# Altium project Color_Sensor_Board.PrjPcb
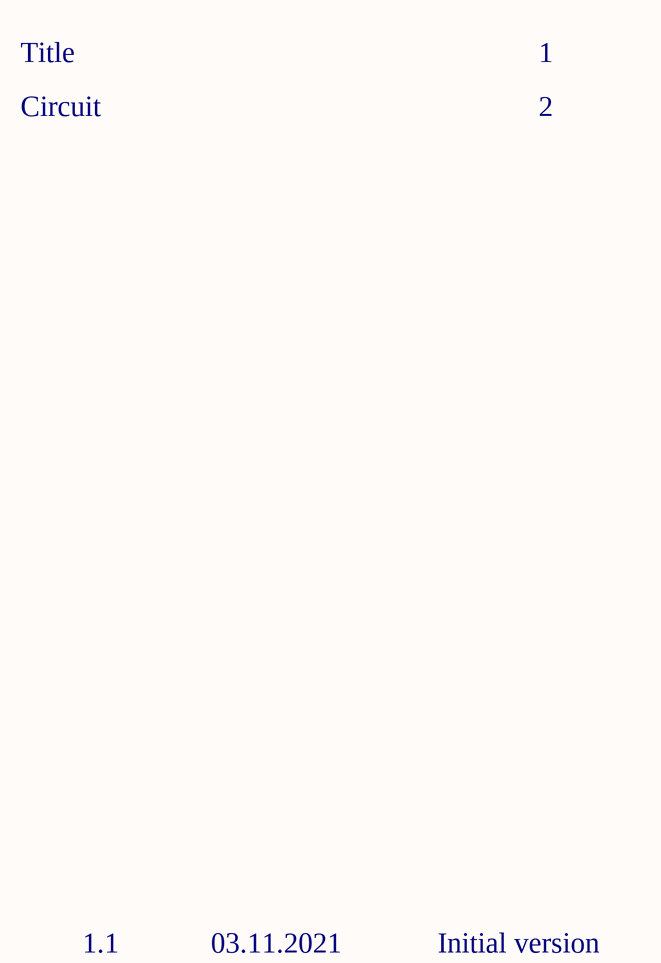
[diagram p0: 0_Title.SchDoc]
2 sheets, 38 parts. Net scope: global (net labels, ports and power ports of the same name join across sheets).
Board file: Color_Sensor_Board.PcbDoc
Sheets:
  0_Title.SchDoc
  1_Circuit.SchDoc

## Sheet 0_Title.SchDoc: Title
size A2; Author: Aleksandr Dudko; Engineer: Engineer; Organization: Softeq Development; Revision: 1.1.2; SheetNumber: 1; SheetTotal: 2; Project: Color_Sensor_Board; Reviewed: YES; Approved: YES

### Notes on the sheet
- Title
- 1
- Circuit
- 2
- 1.1
- 03.11.2021
- Initial version

## Sheet 1_Circuit.SchDoc: Circuit
size A2; Author: Aleksandr Dudko; Engineer: Engineer; Organization: Softeq Development; Revision: 1.1.2; SheetNumber: 2; SheetTotal: 2; Project: Color_Sensor_Board; Reviewed: YES; Approved: YES
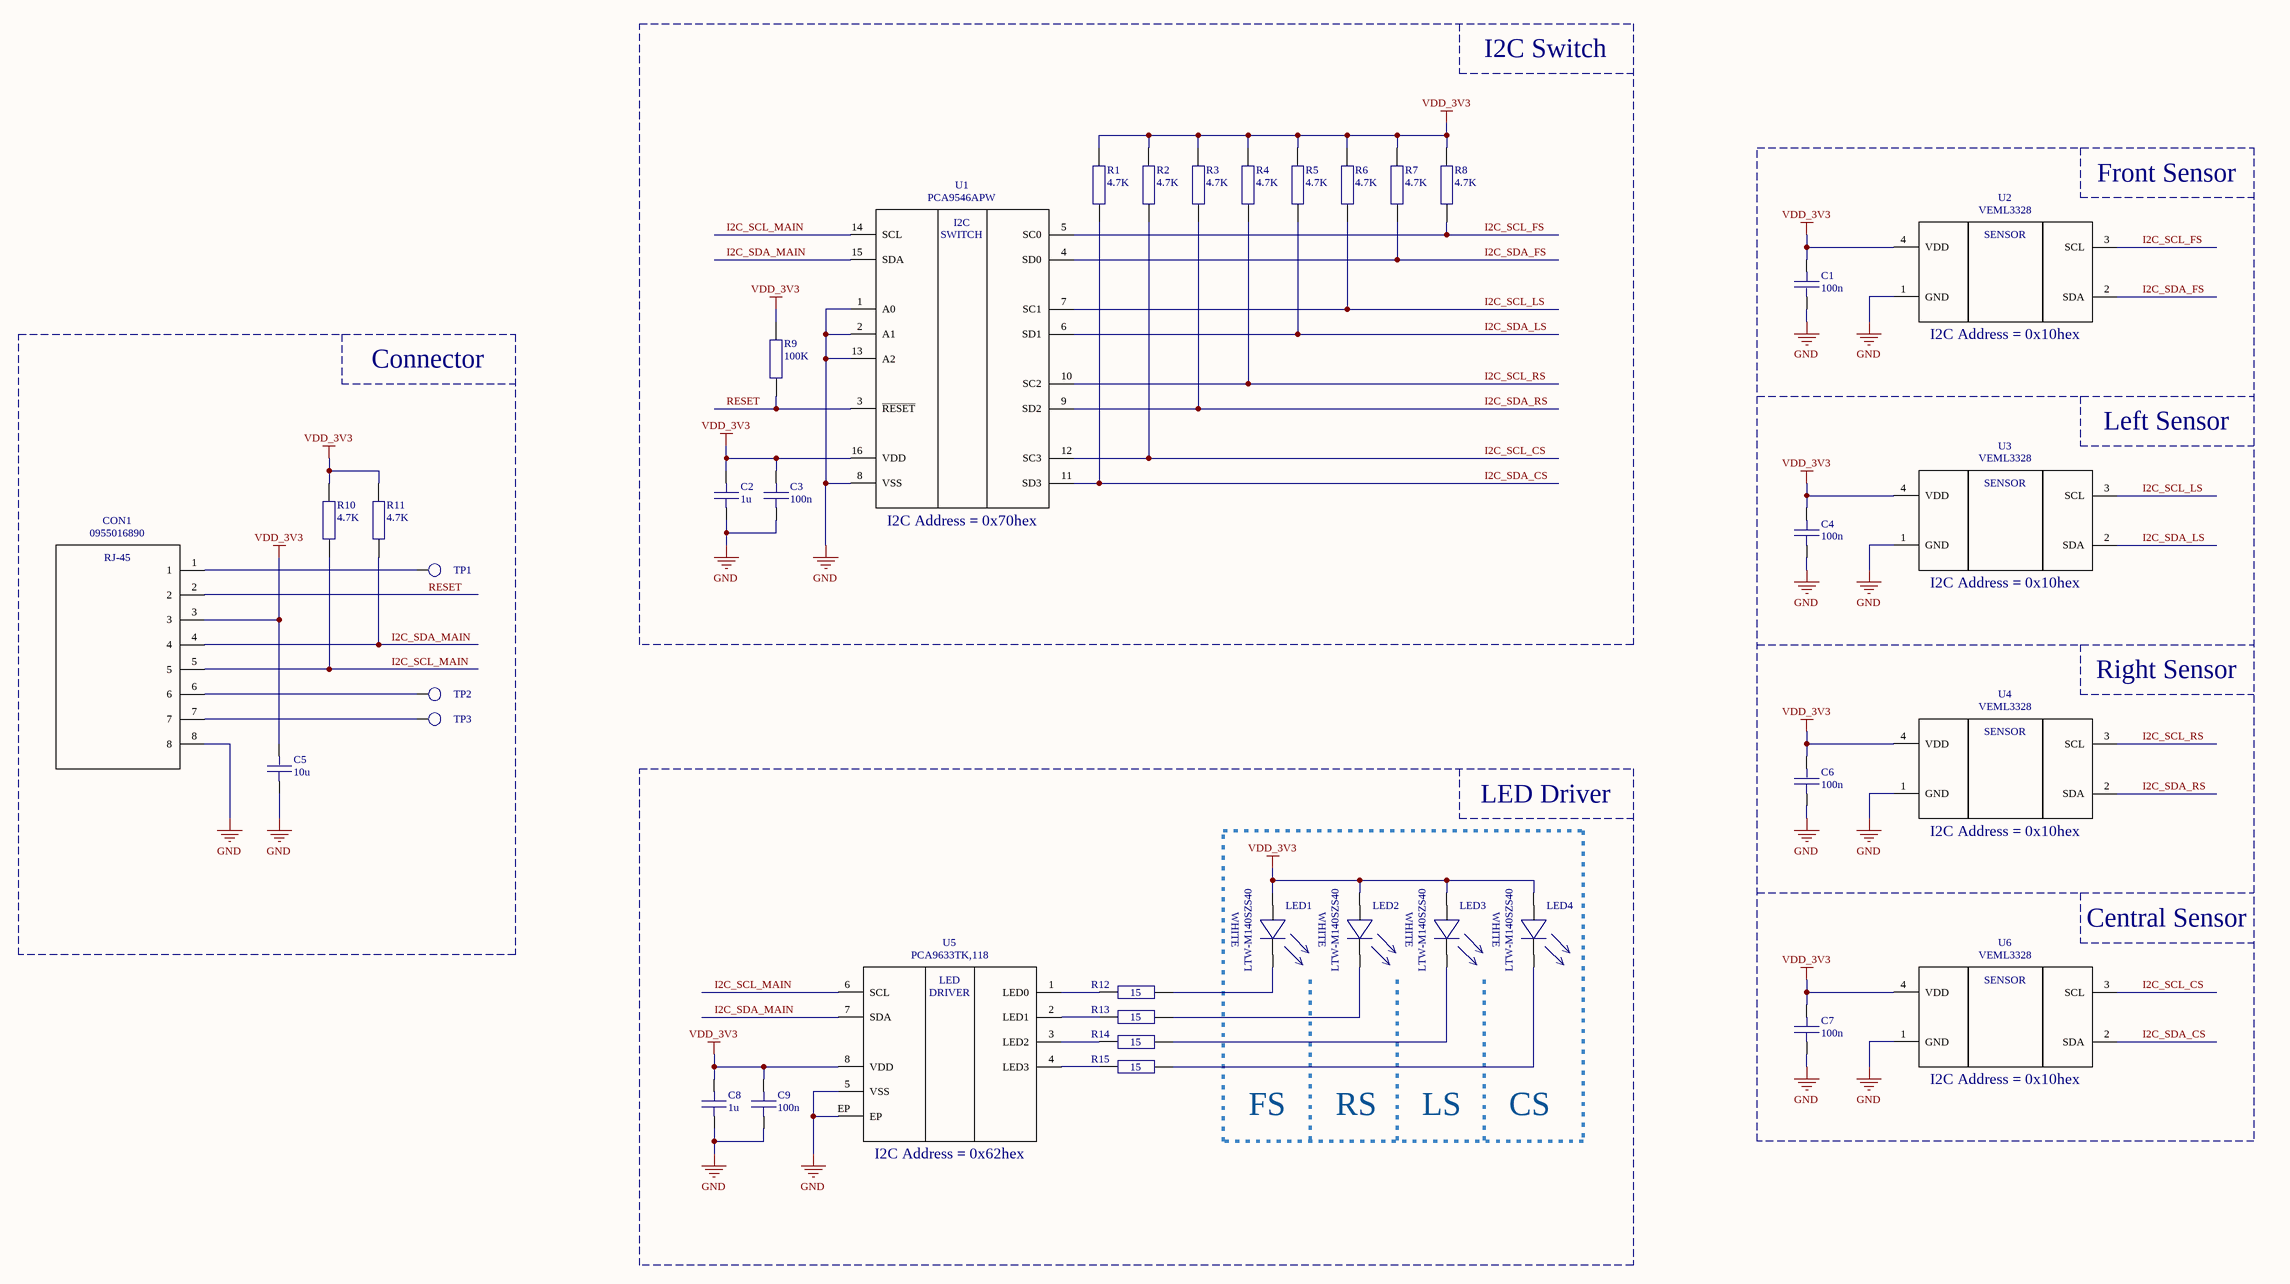
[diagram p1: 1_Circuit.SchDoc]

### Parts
C1  value 100n  [C_0402]  (hidden comment: CC0402KRX7R7BB104)
C2  value 1u  [C_0402]  (hidden comment: CC0402KRX5R7BB105)
C3  value 100n  [C_0402]  (hidden comment: CC0402KRX7R7BB104)
C4  value 100n  [C_0402]  (hidden comment: CC0402KRX7R7BB104)
C5  value 10u  [C_0402]  (hidden comment: C0402C106M9PAC7867)
C6  value 100n  [C_0402]  (hidden comment: CC0402KRX7R7BB104)
C7  value 100n  [C_0402]  (hidden comment: CC0402KRX7R7BB104)
C8  value 1u  [C_0402]  (hidden comment: CC0402KRX5R7BB105)
C9  value 100n  [C_0402]  (hidden comment: CC0402KRX7R7BB104)
CON1  0955016890  [Molex_955016890]
LED1  LTW-M140SZS40  [Lite-On_LTW-M140SZS40]
LED2  LTW-M140SZS40  [Lite-On_LTW-M140SZS40]
LED3  LTW-M140SZS40  [Lite-On_LTW-M140SZS40]
LED4  LTW-M140SZS40  [Lite-On_LTW-M140SZS40]
R1  value 4.7K  [R_0402]  (hidden comment: RC0402FR-074K7L)
R2  value 4.7K  [R_0402]  (hidden comment: RC0402FR-074K7L)
R3  value 4.7K  [R_0402]  (hidden comment: RC0402FR-074K7L)
R4  value 4.7K  [R_0402]  (hidden comment: RC0402FR-074K7L)
R5  value 4.7K  [R_0402]  (hidden comment: RC0402FR-074K7L)
R6  value 4.7K  [R_0402]  (hidden comment: RC0402FR-074K7L)
R7  value 4.7K  [R_0402]  (hidden comment: RC0402FR-074K7L)
R8  value 4.7K  [R_0402]  (hidden comment: RC0402FR-074K7L)
R9  value 100K  [R_0402]  (hidden comment: RC0402FR-07100KL)
R10  value 4.7K  [R_0402]  (hidden comment: RC0402FR-074K7L)
R11  value 4.7K  [R_0402]  (hidden comment: RC0402FR-074K7L)
R12  value 15  [R_0402]  (hidden comment: RC0402FR-0715RL)
R13  value 15  [R_0402]  (hidden comment: RC0402FR-0715RL)
R14  value 15  [R_0402]  (hidden comment: RC0402FR-0715RL)
R15  value 15  [R_0402]  (hidden comment: RC0402FR-0715RL)
TP1  SolderPoint_1.2  [SSP_1.2]  (value not drawn)  (no BOM)
TP2  SolderPoint_1.2  [SSP_1.2]  (value not drawn)  (no BOM)
TP3  SolderPoint_1.2  [SSP_1.2]  (value not drawn)  (no BOM)
U1  PCA9546APW  [TSSOP-16[8-8]_0.45_0.65_4.4x5x1.1]
U2  VEML3328  [Vishay_VEML3328]
U3  VEML3328  [Vishay_VEML3328]
U4  VEML3328  [Vishay_VEML3328]
U5  PCA9633TK,118  [SON-8[4-4]_0.3_0.5_3x3x0.8_EP[1.65x2.25]]
U6  VEML3328  [Vishay_VEML3328]

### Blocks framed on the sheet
I2C Switch: C2 C3 R1-R9 U1
Connector: C5 CON1 R10 R11 TP1-TP3

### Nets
GND: C1.1 C2.1 C3.1 C4.1 C5.1 C6.1 C7.1 C8.1 C9.1 CON1.8 U1.1(A0) U1.2(A1) U1.8(VSS) U1.13(A2) U2.1(GND) U3.1(GND) U4.1(GND) U5.5(VSS) U5.EP U6.1(GND)
VDD_3V3: C1.2 C2.2 C3.2 C4.2 C5.2 C6.2 C7.2 C8.2 C9.2 CON1.3 LED1.A LED2.A LED3.A LED4.A R1.2 R2.2 R3.2 R4.2 R5.2 R6.2 R7.2 R8.2 R9.2 R10.2 R11.2 U1.16(VDD) U2.4(VDD) U3.4(VDD) U4.4(VDD) U5.8(VDD) U6.4(VDD)
I2C_SCL_CS: R2.1 U1.12(SC3) U6.3(SCL)
I2C_SCL_FS: R8.1 U1.5(SC0) U2.3(SCL)
I2C_SCL_LS: R6.1 U1.7(SC1) U3.3(SCL)
I2C_SCL_MAIN: CON1.5 R10.1 U1.14(SCL) U5.6(SCL)
I2C_SCL_RS: R4.1 U1.10(SC2) U4.3(SCL)
I2C_SDA_CS: R1.1 U1.11(SD3) U6.2(SDA)
I2C_SDA_FS: R7.1 U1.4(SD0) U2.2(SDA)
I2C_SDA_LS: R5.1 U1.6(SD1) U3.2(SDA)
I2C_SDA_MAIN: CON1.4 R11.1 U1.15(SDA) U5.7(SDA)
I2C_SDA_RS: R3.1 U1.9(SD2) U4.2(SDA)
RESET: CON1.2 R9.1 U1.3(~{RESET})
NetCON1_1: CON1.1 TP1.1
NetCON1_6: CON1.6 TP2.1
NetCON1_7: CON1.7 TP3.1
NetLED1_C: LED1.C R12.2
NetLED2_C: LED2.C R13.2
NetLED3_C: LED3.C R14.2
NetLED4_C: LED4.C R15.2
NetR12_1: R12.1 U5.1(LED0)
NetR13_1: R13.1 U5.2(LED1)
NetR14_1: R14.1 U5.3(LED2)
NetR15_1: R15.1 U5.4(LED3)

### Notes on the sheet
- Front Sensor
- (near U2) I2C Address = 0x10hex
- Left Sensor
- (near U1) I2C Address = 0x70hex
- (near U3) I2C Address = 0x10hex
- Right Sensor
- LED Driver
- (near U4) I2C Address = 0x10hex
- Central Sensor
- FS
- RS
- LS
- CS
- (near U6) I2C Address = 0x10hex
- (near U5) I2C Address = 0x62hex

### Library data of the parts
C1 C3 C4 C6 C7 C9 = CC0402KRX7R7BB104: Capacitor, 100nF, 16V, X7R, 10%, -55/+125,0402; Manufacturer: Yageo
C2 C8 = CC0402KRX5R7BB105: Capacitor, 1uF, 16V, X5R, 10%, -55/+85, 0402; Manufacturer: Yageo
C5 = C0402C106M9PAC7867: Capacitor, 10uF, 6.3V, 20%, X5R, -55/+85 0402; Manufacturer: Kemet
CON1 = 0955016890: Conn, RJ-45, Unshielded, P-1.27mm, RA, -40/+85, SMD; Manufacturer: Molex
LED1-LED4 = LTW-M140SZS40: Diode, LED, White, 20mA, 3.2V, -30/+85, 3.0x1.4x1.2mm; Manufacturer: Lite-On
R1-R8 R10 R11 = RC0402FR-074K7L: Resistor, 4.7K, 1%, 0.063W, -55/+155, 0402; Manufacturer: Yageo
R9 = RC0402FR-07100KL: Resistor, 100K, 1%, 0.063W, -55/+155, 0402; Manufacturer: Yageo
R12-R15 = RC0402FR-0715RL: Resistor, 15, 1%, 0.0625W, -55/+155, 0402; Manufacturer: Yageo
TP1-TP3 = SolderPoint_SMD_1.2: Solder Point, 1.2mm, SMD
U1 = PCA9546APW: IC, I2C/SMBus Switch, 4Ch, 400kHz, -40/+85, TSSOP-16; Manufacturer: NXP
U2-U4 U6 = VEML3328: IC, Color Sensor, RGBCIR, I2C/SMBus, 2.6-3.6V, -40/+85, SMD; Manufacturer: Vishay
U5 = PCA9633TK,118: IC, LED Driver, 4Ch, 2.3-5.5V, 25mA/Ch, 100mAmax, -40/+85, HVSON-8; Manufacturer: NXP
